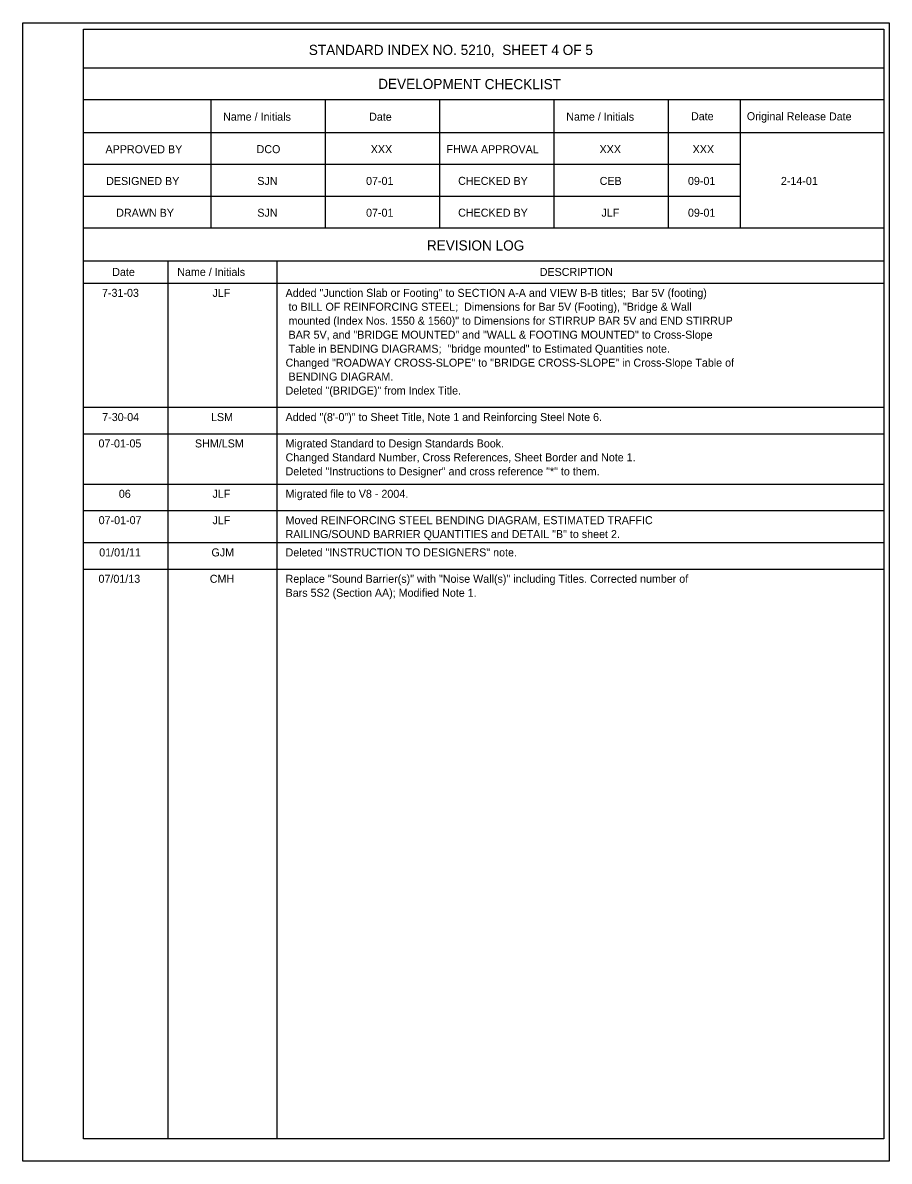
# Model space of a CAD drawing. Extents: x 120632.7 to 120668.8, y 120715.7 to 120740.6.
# Drawn here: x 120657.86 to 120668.77, y 120718.77 to 120733.1 of the extents above; entities that cross this region are included whole.
import ezdxf

# ---------------------------------------------------------------- set-up
doc = ezdxf.new("R2010")
doc.units = 0
for name, color, linetype in [('Border', 7, 'Continuous'), ('PlotBorder_dp', 7, 'Continuous'), ('TextStructures', 7, 'Continuous')]:
    doc.layers.add(name, color=color, linetype=linetype)

msp = doc.modelspace()

# ---------------------------------------------------------------- linework, layer by layer
at = {"layer": 'Border'}
for p, q in [((120668.701, 120732.529), (120658.628, 120732.529)), ((120668.701, 120732.129), (120658.628, 120732.129)), ((120660.228, 120732.129), (120660.228, 120730.515)), ((120661.668, 120732.129), (120661.668, 120730.515)), ((120663.108, 120732.129), (120663.108, 120730.515)), ((120664.548, 120732.129), (120664.548, 120730.515)), ((120665.988, 120732.129), (120665.988, 120730.515)), ((120666.895, 120732.129), (120666.895, 120730.515)), ((120668.701, 120731.715), (120658.628, 120731.715)), ((120666.895, 120731.315), (120658.628, 120731.315)), ((120666.895, 120730.915), (120658.628, 120730.915)), ((120668.701, 120730.515), (120658.628, 120730.515)), ((120668.701, 120730.101), (120658.628, 120730.101)), ((120659.688, 120730.101), (120659.688, 120719.048)), ((120661.059, 120730.101), (120661.059, 120719.048)), ((120668.701, 120729.819), (120658.628, 120729.819)), ((120668.701, 120728.255), (120658.628, 120728.255)), ((120668.701, 120727.923), (120658.628, 120727.923)), ((120668.701, 120727.289), (120658.628, 120727.289)), ((120668.701, 120726.957), (120658.628, 120726.957)), ((120668.701, 120726.551), (120658.628, 120726.551)), ((120668.701, 120726.219), (120658.628, 120726.219))]:
    msp.add_line(p, q, dxfattribs=at)
msp.add_lwpolyline([(120658.628, 120733.019), (120668.701, 120733.019), (120668.701, 120719.048), (120658.628, 120719.048)], close=True, dxfattribs=at)
at = {"layer": 'PlotBorder_dp'}
msp.add_line((120657.863, 120718.767), (120657.863, 120718.767), dxfattribs=at)
msp.add_lwpolyline([(120657.863, 120733.101), (120668.769, 120733.101), (120668.769, 120718.767), (120657.863, 120718.767)], close=True, dxfattribs=at)

# ---------------------------------------------------------------- texts
at = {"layer": 'TextStructures'}
for s, height, p in [('STANDARD INDEX NO. 5210,  SHEET 4 OF 5', 0.128, (120661.463, 120732.695)), ('DCO', 0.1008, (120660.806, 120731.459)), ('XXX', 0.1008, (120662.243, 120731.459)), ('XXX', 0.1008, (120665.123, 120731.459)), ('XXX', 0.1008, (120666.295, 120731.459)), ('SJN', 0.1008, (120660.815, 120731.059)), ('07-01', 0.1008, (120662.184, 120731.059)), ('CEB', 0.1008, (120665.125, 120731.059)), ('09-01', 0.1008, (120666.236, 120731.059)), ('2-14-01', 0.1008, (120667.406, 120731.059)), ('SJN', 0.1008, (120660.815, 120730.659)), ('07-01', 0.1008, (120662.184, 120730.659)), ('JLF', 0.1008, (120665.148, 120730.659)), ('09-01', 0.1008, (120666.236, 120730.659)), ('DESCRIPTION', 0.1008, (120664.37, 120729.913)), ('7-31-03', 0.1008, (120658.86, 120729.65)), ('JLF', 0.1008, (120660.251, 120729.65)), ('Added "Junction Slab or Footing" to SECTION A-A and VIEW B-B titles;  Bar 5V (footing) ', 0.1008, (120661.171, 120729.65)), (' to BILL OF REINFORCING STEEL;  Dimensions for Bar 5V (Footing), "Bridge & Wall ', 0.1008, (120661.171, 120729.475)), (' mounted (Index Nos. 1550 & 1560)" to Dimensions for STIRRUP BAR 5V and END STIRRUP ', 0.1008, (120661.171, 120729.299)), (' BAR 5V, and "BRIDGE MOUNTED" and "WALL & FOOTING MOUNTED" to Cross-Slope ', 0.1008, (120661.171, 120729.123)), (' Table in BENDING DIAGRAMS;  "bridge mounted" to Estimated Quantities note.  ', 0.1008, (120661.171, 120728.947)), ('Changed "ROADWAY CROSS-SLOPE" to "BRIDGE CROSS-SLOPE" in Cross-Slope Table of ', 0.1008, (120661.171, 120728.771)), (' BENDING DIAGRAM.', 0.1008, (120661.171, 120728.596)), ('Deleted "(BRIDGE)" from Index Title.', 0.1008, (120661.171, 120728.42)), ('7-30-04', 0.1008, (120658.863, 120728.086)), ('LSM', 0.1008, (120660.232, 120728.086)), ('Added "(8\'-0")" to Sheet Title, Note 1 and Reinforcing Steel Note 6.', 0.1008, (120661.171, 120728.086)), ('07-01-05', 0.1008, (120658.816, 120727.754)), ('SHM/LSM', 0.1008, (120660.03, 120727.754)), ('Migrated Standard to Design Standards Book.', 0.1008, (120661.171, 120727.754)), ('Changed Standard Number, Cross References, Sheet Border and Note 1.', 0.1008, (120661.171, 120727.579)), ('Deleted "Instructions to Designer" and cross reference "*" to them. ', 0.1008, (120661.171, 120727.403)), ('06', 0.1008, (120659.072, 120727.12)), ('JLF', 0.1008, (120660.251, 120727.12)), ('Migrated file to V8 - 2004.', 0.1008, (120661.171, 120727.12)), ('07-01-07', 0.1008, (120658.818, 120726.788)), ('JLF', 0.1008, (120660.251, 120726.788)), ('Moved REINFORCING STEEL BENDING DIAGRAM, ESTIMATED TRAFFIC ', 0.1008, (120661.171, 120726.788)), ('RAILING/SOUND BARRIER QUANTITIES and DETAIL "B" to sheet 2.', 0.1008, (120661.171, 120726.613)), ('01/01/11', 0.1008, (120658.825, 120726.382)), ('GJM', 0.1008, (120660.238, 120726.382)), ('Deleted "INSTRUCTION TO DESIGNERS" note.', 0.1008, (120661.171, 120726.382)), ('07/01/13', 0.1008, (120658.816, 120726.05)), ('CMH', 0.1008, (120660.217, 120726.05)), ('Replace "Sound Barrier(s)" with "Noise Wall(s)" including Titles. Corrected number of', 0.1008, (120661.171, 120726.05)), ('Bars 5S2 (Section AA); Modified Note 1.', 0.1008, (120661.171, 120725.874))]:
    msp.add_text(s, height=height, dxfattribs=at).set_placement(p)
for s, height, p in [('DEVELOPMENT CHECKLIST', 0.128, (120662.336, 120732.268)), ('Name / Initials', 0.1008, (120660.384, 120731.869)), ('Date', 0.1008, (120662.222, 120731.868)), ('Name / Initials', 0.1008, (120664.704, 120731.869)), ('Date', 0.1008, (120666.274, 120731.874)), ('Original Release Date', 0.1008, (120666.977, 120731.874)), ('APPROVED BY', 0.1008, (120658.904, 120731.459)), ('FHWA APPROVAL', 0.1008, (120663.196, 120731.46)), ('DESIGNED BY', 0.1008, (120658.912, 120731.059)), ('CHECKED BY', 0.1008, (120663.343, 120731.06)), ('DRAWN BY', 0.1008, (120659.039, 120730.659)), ('CHECKED BY', 0.1008, (120663.343, 120730.66)), ('REVISION LOG', 0.128, (120662.949, 120730.235)), ('Date', 0.1008, (120658.989, 120729.913)), ('Name / Initials', 0.1008, (120659.807, 120729.914))]:
    msp.add_text(s, height=height, rotation=359.8756, dxfattribs=at).set_placement(p)

doc.saveas('drawing.dxf')
